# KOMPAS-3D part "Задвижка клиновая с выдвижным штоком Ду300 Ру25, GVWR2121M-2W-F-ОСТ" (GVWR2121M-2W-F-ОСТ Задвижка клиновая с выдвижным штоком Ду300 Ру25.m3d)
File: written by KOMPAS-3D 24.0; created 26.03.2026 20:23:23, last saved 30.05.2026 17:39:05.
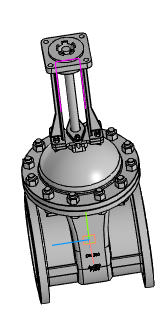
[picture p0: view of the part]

Document properties: Автор: R2D2; Полное имя файла: E:\Работа\Зайцев\GVWR2121M-2W-F-ОСТ Задвижка клиновая 30с964нж DN.ru Ду50-300 Ру25\исходные материалы\DN300\GVWR2121M-2W-F-ОСТ Задвижка клиновая с выдвижным штоком Ду300 Ру25.m3d

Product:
- Component [detail]: AS 1110 - M10 x 35  | qty 4  | pos. 2  | Комментарий: Болты и винты   шестигранные точные   метрические ISO; Автор: R2D2; additional columns: Сталь, мягкая; source file: AS 1110 - M10 x 35 AS 1110 - M10 x 35.m3d
- Component [detail]: ANSI B18.2.4.2M - M10x1,5 - 16  | designation ANSI B18.2.4.2M - M10x1,5  | qty 4  | pos. 3  | Комментарий: Типы метрических   шестигранных гаек   2; Автор: R2D2; additional columns: Сталь, мягкая; source file: ANSI B18.2.4.2M - M10x1,5 ANSI B18.2.4.2M - M10x1,5 - 16.m3d
- Component [detail]: ANSI B18.2.4.2M - M8x1,25 - 13  | designation ANSI B18.2.4.2M - M8x1,25  | qty 1  | pos. 4  | Комментарий: Типы метрических   шестигранных гаек   2; Автор: R2D2; additional columns: Сталь, мягкая; source file: ANSI B18.2.4.2M - M8x1,25 ANSI B18.2.4.2M - M8x1,25 - 13.m3d
- Component [detail]: ANSI B18.2.4.2M - M20x2,5 - 30  | designation ANSI B18.2.4.2M - M20x2,5  | qty 12  | pos. 5  | Комментарий: Типы метрических   шестигранных гаек   2; Автор: R2D2; additional columns: Сталь, мягкая; source file: ANSI B18.2.4.2M - M20x2,5 ANSI B18.2.4.2M - M20x2,5 - 30.m3d
- Component [detail]: AS 1110 - M20 x 70  | qty 12  | pos. 6  | Комментарий: Болты и винты   шестигранные точные   метрические ISO; Автор: R2D2; additional columns: Сталь, мягкая; source file: AS 1110 - M20 x 70 AS 1110 - M20 x 70.m3d
- Component [detail]: Деталь1  | qty 1  | pos. 7  | Автор: R2D2; additional columns: Типовые; source file: 2.m3d
- Component [detail]: ANSI B18.2.4.2M - M8x1,25 - 13  | designation ANSI B18.2.4.2M - M8x1,25-01  | qty 1  | pos. 8  | Комментарий: Типы метрических   шестигранных гаек   2; Автор: R2D2; additional columns: Сталь, мягкая; source file: ANSI B18.2.4.2M - M8x1,25 ANSI B18.2.4.2M - M8x1,25 - 13.m3d
- Component [detail]: Фланец  | qty 2  | pos. 7  | Автор: R2D2; additional columns: Типовые; source file: Фланец DN300 Pn25 b40.m3d
- Component [detail]: Деталь1  | qty 1  | pos. 9  | additional columns: Типовые; source file: Фланец В.m3d
- Body: Тело 1  | qty 1
    Масса: 559.952517
- Body: Тело 2  | qty 1
    Масса: 559.952517
- Part/product: Задвижка клиновая с выдвижным штоком Ду300 Ру25  | designation GVWR2121M-2W-F-ОСТ
    Масса: 270
    Раздел спецификации: Прочие изделия
    Примечание: D040-07881

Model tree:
1. Массив по концентрической сетке:1  (labels: Грань.Твердое тело1)  (12 pattern instances)
     Шаг 2 = 360
2. Массив по сетке:1  (labels: Грань.Твердое тело1)  (4 pattern instances)
     Шаг 1 = 50; Угол раствора = 90; Шаг 2 = 120
3. Масштабирование:1
4. Масштабирование : Твердое тело1
5. Масштабирование : Solid1  (labels: Твердое тело1; Solid1)
     Масштаб по оси Х = 1; Масштаб по оси Y = 1; Масштаб по оси Z = 1; Коэффициент = 1.5
6. Эскиз:1  (with: Вершина.Элемент выдавливания:2)
7. Элемент по траектории:1  (with: Грань.Элемент выдавливания:2)
     Длина траектории = 679.228
8. Элемент выдавливания:1  (with: Грань.Элемент по траектории:1, Грань.Элемент вращения:1)
     Расстояние 1 = 21.6625
9. Элемент выдавливания:2  (with: Грань.Элемент по траектории:1, Грань.Элемент вращения:1)
     Расстояние 1 = 11.3947
10. Скругление:1  (with: Ребро.Элемент выдавливания:2, Ребро.Элемент выдавливания:1)
     Радиус = 10
11. Элемент выдавливания:3  (with: Грань.Элемент по траектории:1)
     Расстояние 1 = 354.258
12. Эскиз:2  (with: Ребро.Элемент выдавливания:2)
13. Элемент вращения:1
     Угол 1 = 360
14. Зеркальный массив:1
15. Экземпляр ( 1 )
16. Экземпляр ( 2 )  (with: Элемент вращения:1)
17. Фаска:1  (with: Ребро.Элемент вращения:1)  (labels: Ребро.Элемент вращения:1.Экземпляр ( 2 ))
     Угол = 45; Длина 1 = 4; Длина 2 = 4
18. Эскиз:3
19. Элемент выдавливания:4  (with: Грань.Элемент по траектории:1, Грань.Элемент вращения:1, Грань.Элемент выдавливания:1, Грань.Элемент выдавливания:2, Грань.Элемент выдавливания:4)  (labels: Грань.Твердое тело1; Грань.Solid1; Solid1; Твердое тело1)
     Расстояние 1 = 188.5; Смещение 1 = 1; Ориентация = 2; Расстояние = -250; Ориентация = 2; Расстояние = -1100

Expressions: 375+8
Referenced files in E:\Работа\Зайцев\GVWR2121M-2W-F-ОСТ Задвижка клиновая 30с964нж DN.ru Ду50-300 Ру25\исходные материалы\DN300\: AS 1110 - M10 x 35 AS 1110 - M10 x 35.m3d, ANSI B18.2.4.2M - M10x1,5 ANSI B18.2.4.2M - M10x1,5 - 16.m3d, ANSI B18.2.4.2M - M8x1,25 ANSI B18.2.4.2M - M8x1,25 - 13.m3d, ANSI B18.2.4.2M - M20x2,5 ANSI B18.2.4.2M - M20x2,5 - 30.m3d, AS 1110 - M20 x 70 AS 1110 - M20 x 70.m3d, 2.m3d, Фланец DN300 Pn25 b40.m3d, Фланец В.m3d
Referenced files in E:\Работа\Зайцев\GVWR3131M-2W-F-S Задвижка клиновая с выдвижным штоком DN.ru Ду50-200 Ру63\DN200\исходные материалы\: ANSI B18.2.4.2M - M20x2,5 ANSI B18.2.4.2M - M20x2,5 - 30.m3d, AS 1110 - M20 x 70 AS 1110 - M20 x 70.m3d, ANSI B18.2.4.2M - M10x1,5 ANSI B18.2.4.2M - M10x1,5 - 16.m3d, AS 1110 - M10 x 35 AS 1110 - M10 x 35.m3d
Referenced files in E:\Работа\Зайцев\GVWR2434M-2W-F-ОСТ Задвижка клиновая с выдвижным штоком DN.ru Ду50-300 Ру25\исходные материалы\DN300\: Фланец DN300 Pn25 b40.m3d
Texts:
  GVWR2121M-2W-F-ОСТ
  Ду300
  GOST 26.020 Pr3
  Ру25
  AS 1110 - M10 x 35 AS 1110 - M10 x 35 (1)
  ANSI B18.2.4.2M - M10x1,5 ANSI B18.2.4.2M - M10x1,5 - 16 (1)
  ANSI B18.2.4.2M - M8x1,25 ANSI B18.2.4.2M - M8x1,25 - 13
  ANSI B18.2.4.2M - M20x2,5 ANSI B18.2.4.2M - M20x2,5 - 30 (1)
  AS 1110 - M20 x 70 AS 1110 - M20 x 70 (1)
  Деталь1 Деталь1
  ANSI B18.2.4.2M - M20x2,5 ANSI B18.2.4.2M - M20x2,5 - 30 (2)
  AS 1110 - M20 x 70 AS 1110 - M20 x 70 (2)
  ANSI B18.2.4.2M - M20x2,5 ANSI B18.2.4.2M - M20x2,5 - 30 (3)
  AS 1110 - M20 x 70 AS 1110 - M20 x 70 (3)
  ANSI B18.2.4.2M - M20x2,5 ANSI B18.2.4.2M - M20x2,5 - 30 (4)
  AS 1110 - M20 x 70 AS 1110 - M20 x 70 (4)
  ANSI B18.2.4.2M - M20x2,5 ANSI B18.2.4.2M - M20x2,5 - 30 (5)
  AS 1110 - M20 x 70 AS 1110 - M20 x 70 (5)
  ANSI B18.2.4.2M - M20x2,5 ANSI B18.2.4.2M - M20x2,5 - 30 (6)
  AS 1110 - M20 x 70 AS 1110 - M20 x 70 (6)
  ANSI B18.2.4.2M - M20x2,5 ANSI B18.2.4.2M - M20x2,5 - 30 (7)
  AS 1110 - M20 x 70 AS 1110 - M20 x 70 (7)
  ANSI B18.2.4.2M - M20x2,5 ANSI B18.2.4.2M - M20x2,5 - 30 (8)
  AS 1110 - M20 x 70 AS 1110 - M20 x 70 (8)
  ANSI B18.2.4.2M - M20x2,5 ANSI B18.2.4.2M - M20x2,5 - 30 (9)
  AS 1110 - M20 x 70 AS 1110 - M20 x 70 (9)
  ANSI B18.2.4.2M - M20x2,5 ANSI B18.2.4.2M - M20x2,5 - 30 (10)
  AS 1110 - M20 x 70 AS 1110 - M20 x 70 (10)
  ANSI B18.2.4.2M - M20x2,5 ANSI B18.2.4.2M - M20x2,5 - 30 (11)
  AS 1110 - M20 x 70 AS 1110 - M20 x 70 (11)
  ANSI B18.2.4.2M - M20x2,5 ANSI B18.2.4.2M - M20x2,5 - 30 (12)
  AS 1110 - M20 x 70 AS 1110 - M20 x 70 (12)
  ANSI B18.2.4.2M - M10x1,5 ANSI B18.2.4.2M - M10x1,5 - 16 (2)
  AS 1110 - M10 x 35 AS 1110 - M10 x 35 (2)
  ANSI B18.2.4.2M - M10x1,5 ANSI B18.2.4.2M - M10x1,5 - 16 (3)
  AS 1110 - M10 x 35 AS 1110 - M10 x 35 (3)
  ANSI B18.2.4.2M - M10x1,5 ANSI B18.2.4.2M - M10x1,5 - 16 (4)
  AS 1110 - M10 x 35 AS 1110 - M10 x 35 (4)
  ANSI B18.2.4.2M - M8x1,25-01 ANSI B18.2.4.2M - M8x1,25 - 13
  Фланец (1)
  Фланец (2)
  Ось Y.Начало координат
  Ось Z.Начало координат
  Плоскость ZY.Начало координат
  Плоскость ZX.Начало координат
  Плоскость XY.Начало координат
